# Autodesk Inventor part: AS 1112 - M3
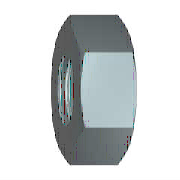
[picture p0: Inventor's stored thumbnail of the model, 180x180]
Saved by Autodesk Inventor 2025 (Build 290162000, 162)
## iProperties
Created: 2024-01
Part Number: AS 1112 - M3
Material: Acciaio, Dolce
Description: Dadi esagonali metrici ISO, inclusi dadi sottili, dadi con intaglio e dadi a corona
Document SubType Name: Modeling
Standard: AS 1112
Designer: Ryzen5700u
Standards Organization: AS
Language: it-IT
Size Designation: M3
Categories: <MemberInstance><Categories><Category DisplayName="Elementi di fissaggio" InternalName="e4da775c-781d-43d5-af7c-5136215cf5a6" Mnemonic="FSTN"><Category DisplayN
Density: 7.85 g/cm^3
Appearance: Semilucidato
IsCustomPart: 0
Author: Ryzen5700u
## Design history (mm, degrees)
body "Solid1"
workaxis "Work Axis1"
workplane "Work Plane1"
sketch "Schizzo1"
  geometry: L1 (-3.175, 0)-(-1.588, 2.75); L2 (-1.588, 2.75)-(1.588, 2.75); L3 (1.588, 2.75)-(3.175, 0); L4 (3.175, 0)-(1.588, -2.75); L5 (1.588, -2.75)-(-1.588, -2.75); L6 (-1.588, -2.75)-(-3.175, 0); 2 further points
  constraints: 12 end point, 1 coincident, 1 horizontal, 11 other
  dimensions: "d0" = 6.35085 distance of L3.end L1.start (= 1.1547 x SW)
extrude "Corpo" new body sketch "Schizzo1" distance "d1" = 1.8 (= KOH); taper "d2" = 0 deg
revolve "Smusso1" stored, may be unused: angle "d7" = 90 deg
sketch "Schizzo3"
  geometry: A1 r 2.75 centre (0, 0) between (-1.375, -2.382) and (1.375, -2.382) reference; 1 further point
  constraints: 1 coincident
hole "Filettatura" sketch "Schizzo3" diameter "d25" = 2.459; stored, may be unused: countersink angle "d29" = 82 deg, drill point angle "d31" = 118 deg; dims "d26" = 6, "d27" = 4, "d28" = 2, "d30" = 8
chamfer "Smusso2" distance "d8" = 0.27063 (= -0.5 x GD1 + 0.5 x NND); stored, may be unused: angle "d9" = 30 deg, second distance "d40" = 0.27063 (= -0.5 x GD1 + 0.5 x NND)
chamfer "Smusso3" distance "d10" = 0.27063 (= -0.5 x GD1 + 0.5 x NND); stored, may be unused: angle "d11" = 30 deg, second distance "d41" = 0.27063 (= -0.5 x GD1 + 0.5 x NND)
sketch "Schizzo2"
  geometry: L1 (0, 1.588)-(0, 3.175) reference; L2 (0, 3.175)-(1.8, 3.175) reference; L3 (1.8, 1.588)-(1.8, 3.175) reference; L4 (-0.36, 0)-(2.16, 0) reference; L5 (0.246, 3.175)-(0, 2.75); L6 (1.554, 3.175)-(1.8, 2.75)
  constraints: 4 end point, 4 point on line
  dimensions: "d3" = 30 deg angle of L1 L5 (= ANG1); "d4" = 30 deg angle of L3 L6 (= ANG2); "d5" = 5.5 diameter of L5.end L4 (= SW0); "d6" = 5.5 diameter of L6.end L4 (= SW01)
other parameters: "ANG1" = 30 deg [user parameter; used in 1 equation term], "ANG2" = 30 deg [user parameter; used in 1 equation term], "NND" = 3 [user parameter; used in 4 equation terms], "KOH" = 1.8 [user parameter; used in 1 equation term], "SW" = 5.5 [user parameter; used in 4 equation terms], "SW0" = 5.5 (= SW) [user parameter; used in 1 equation term], "SW01" = 5.5 (= SW) [user parameter; used in 1 equation term], "GD1" = 2.45873 (computed from THREADDIA, PTC, TOA) [user parameter; used in 4 equation terms], "d13" = 0, "d14" = 0, "d39" = 0, "d42" = 0, "GUL" = 0.27063 (= 0.541266 x PTC) [user parameter], "THREADDIA" = 3 [user parameter; used in 1 equation term], "TOA" = 30 deg [user parameter; used in 1 equation term], "PTC" = 0.5 [user parameter; used in 4 equation terms], "E0" = 6.3525 (= 1.155 x SW) [user parameter], "GAL" = 0.27063 (= 0.541266 x PTC) [user parameter]
